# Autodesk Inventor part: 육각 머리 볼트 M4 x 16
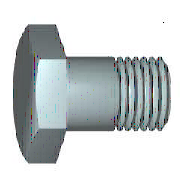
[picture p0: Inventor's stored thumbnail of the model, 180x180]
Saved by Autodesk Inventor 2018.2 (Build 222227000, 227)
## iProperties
IsCustomPart: 0
Created: 2012-02
Part Number: 육각 머리 볼트 M4 x 16
Material: 강철, 연강
Description: 6각 머리 볼트 및 6각 머리 나사
Document SubType Name: Modeling
Standard: KS B 1002
Designer: mduedu
Standards Organization: KS
Language: ko-KR
Size Designation: A + B M4 x 16
Categories: <MemberInstance><Categories><Category DisplayName="조임쇠" InternalName="e4da775c-781d-43d5-af7c-5136215cf5a6" Mnemonic="FSTN"><Category DisplayName="볼트" InternalN
Density: 7.86 g/cm^3
Mass: 2.45486 g
Surface Area: 3.4613 cm^2
Volume: 0.312323 cm^3
Appearance: 강철
Author: mduedu
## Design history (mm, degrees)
sketch "스케치1"
  geometry: L1 (0, 2.94)-(0, 2); L2 (2.1, 2)-(16, 2); L3 (16, 2)-(16, 0); L4 (16, 0)-(-0.4, 0); L5 (-3.68, 0)-(19.28, 0) reference; L6 (-0.4, 0)-(-0.4, 2.94); L7 (-0.4, 2.94)-(0, 2.94); L8 (2.1, 2)-(1.67, 2); L9 (1.67, 2)-(0, 2); L10 (0, -0.588)-(0, 3.528) reference
  constraints: 16 end point, 2 collinear, 2 perpendicular, 1 parallel
  dimensions: "d0" = 16 distance between parallel lines of L3 L1 (= NLG); "d1" = 13.9 distance from line of L2.start L3 (= GEL); "d2" = 4 diameter of L2 L4 (= GD); "d9" = 0.4001 distance between parallel lines of L6 L1 (computed from SD); "d10" = 5.88 diameter of L7 L4 (= SD2); "d13" = 0.42952 distance of L2.start L8.end (computed from GAL); "d14" = 4 diameter of L9 L4 (= BDM)
revolve "본체" sketch "스케치1" stored, may be unused: angle "d12" = 90 deg
sketch "스케치2"
  geometry: L1 (0, 4.041)-(3.5, 2.021); L2 (3.5, 2.021)-(3.5, -2.021); L3 (3.5, -2.021)-(0, -4.041); L4 (0, -4.041)-(-3.5, -2.021); L5 (-3.5, -2.021)-(-3.5, 2.021); L6 (-3.5, 2.021)-(0, 4.041); 2 further points
  constraints: 12 end point, 1 coincident, 1 vertical, 11 other
  dimensions: "d11" = 7 distance between parallel lines of L5 L2 (= SW)
extrude "머리" join sketch "스케치2" distance "d3" = 2.4 (= KOH - SD); taper "d4" = 0 deg
sketch "스케치4"
  geometry: L1 (-2.8, 3.5)-(-2.8, 4.041); L2 (-2.8, 4.041)-(-2.487, 4.041); L3 (-2.487, 4.041)-(-2.8, 3.5); L4 (-3.28, 0)-(0.08, 0) reference; L5 (-0.4, 4.041)-(-2.8, 4.041) reference; L6 (-2.8, 2.021)-(-2.8, 4.041) reference
  constraints: 6 end point, 2 collinear, 1 perpendicular, 1 vertical
  dimensions: "d5" = 30 deg angle of L3 L1 (= ANG1); "d19" = 7 diameter of L1.start L4 (= SW0)
revolve "모따기1" sketch "스케치4" stored, may be unused: angle "d21" = 90 deg
workplane "Work Plane1"
body "Solid1"
feature "스레드" dims "d15" = 13.9 (= GEL), "d16" = 0
chamfer "모따기2" distance "d6" = 0.42941 (= -0.5 x SPD + 0.5 x GD); stored, may be unused: second distance "d7" = 0.42952 (computed from GUL), angle "d55" = 45 deg
other parameters: "NLG" = 16 [user parameter; used in 1 equation term], "GD" = 4 (= NND) [user parameter; used in 2 equation terms], "BDM" = 4 (= NND) [user parameter; used in 1 equation term], "KOH" = 2.8 [user parameter; used in 1 equation term], "GEL" = 13.9 [user parameter; used in 2 equation terms], "SW" = 7 [user parameter; used in 3 equation terms], "SW0" = 7 (= SW) [user parameter; used in 1 equation term], "SPD" = 3.14117 (= NND - 1.2269 x PTC) [user parameter; used in 1 equation term], "SD2" = 5.88 (= SDH) [user parameter; used in 1 equation term], "SD" = 0.4 [user parameter; used in 2 equation terms], "ANG1" = 30 deg [user parameter; used in 1 equation term], "GAL" = 0.42941 (= 0.61345 x PTC) [user parameter; used in 1 equation term], "GUL" = 0.42941 (= 0.61345 x PTC) [user parameter; used in 1 equation term], "d8" = 0, "RR" = 0.2 [user parameter], "d57" = 0, "d58" = 0, "TPU" = 14.28571 (computed from PTC) [user parameter], "GD1" = 3.14117 (= THREADDIA - 1.2269 x PTC) [user parameter], "THREADDIA" = 4 [user parameter; used in 1 equation term], "SDH" = 5.88 [user parameter; used in 1 equation term], "SDHG" = 2.1 [user parameter], "TOA" = 30 deg [user parameter], "PTC" = 0.7 [user parameter; used in 5 equation terms], "NND" = 4 [user parameter; used in 3 equation terms], "E0" = 8.085 (= 1.155 x SW) [user parameter]
